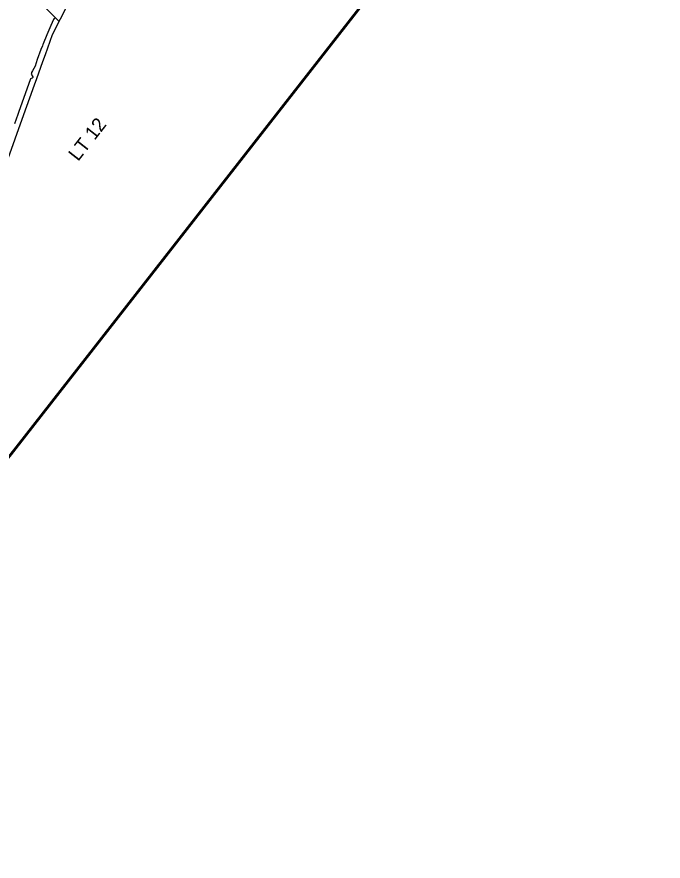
# Model space of a CAD drawing. Extents: x 586326 to 623965, y 4819854 to 4857850.
# Drawn here: x 606308 to 610982, y 4832762 to 4838866 of the extents above; entities that cross this region are included whole.
import ezdxf

# ---------------------------------------------------------------- set-up
doc = ezdxf.new("R2010")
doc.units = 0
for name, color, linetype in [('City Border', 7, 'Continuous'), ('Hydro ROW', 7, 'Continuous'), ('Lots_Concessions', 7, 'Continuous'), ('Major Rds and Hwys', 7, 'Continuous'), ('Municipal Bdry', 7, 'Continuous'), ('STREET NAME INDEX', 7, 'Continuous')]:
    doc.layers.add(name, color=color, linetype=linetype)

msp = doc.modelspace()

# ---------------------------------------------------------------- linework, layer by layer
at = {"layer": 'City Border'}
msp.add_lwpolyline([(586325.7, 4835119.3), (604090.7, 4857849.7), (616179.7, 4848401.5), (598414.7, 4825671.1)], close=True, dxfattribs=at)
at = {"layer": 'Hydro ROW'}
for p, q in [((606553.1, 4838804.2), (606525.7, 4838735.6)), ((606573.3, 4838846.3), (606553.1, 4838804.2)), ((606581.6, 4838853.1), (606573.3, 4838846.3)), ((606525.7, 4838735.6), (606498.6, 4838669.7)), ((606482.5, 4838630.6), (606455.3, 4838556.9)), ((606493.2, 4838656.6), (606482.5, 4838630.6)), ((606496.9, 4838665.7), (606493.2, 4838656.6)), ((606498.6, 4838669.7), (606496.9, 4838665.7)), ((606440.2, 4838508.4), (606421.2, 4838474.9)), ((606455.3, 4838556.9), (606440.2, 4838508.4)), ((606414.8, 4838455.9), (606412, 4838451.2)), ((606412, 4838451.2), (606423.2, 4838433.2)), ((606421.2, 4838474.9), (606414.5, 4838463.2)), ((606414.5, 4838463.2), (606414.8, 4838455.9)), ((606407.4, 4838418.7), (606319.9, 4838173.5)), ((606410.6, 4838420.1), (606407.4, 4838418.7)), ((606417.8, 4838423.4), (606410.6, 4838420.1)), ((606422.8, 4838428.2), (606417.8, 4838423.4)), ((606423.2, 4838433.2), (606422.8, 4838428.2)), ((606314.8, 4838159), (606291.2, 4838091.8)), ((606319.9, 4838173.5), (606314.8, 4838159))]:
    msp.add_line(p, q, dxfattribs=at)
at = {"layer": 'Major Rds and Hwys'}
msp.add_lwpolyline([(606614.3, 4838831.8), (606465.7, 4838981.2)], dxfattribs=at)
at = {"layer": 'Municipal Bdry'}
for p, q in [((606623.7, 4838851.3), (606959.3, 4839512.7)), ((606566, 4838737.6), (606606.3, 4838817)), ((606606.3, 4838817), (606610.2, 4838824.7)), ((606610.2, 4838824.7), (606623.7, 4838851.3)), ((606514.7, 4838594.1), (606566, 4838737.6)), ((606496.2, 4838542.2), (606514.7, 4838594.1)), ((606452.6, 4838420.4), (606496.2, 4838542.2)), ((606347.6, 4838126.4), (606436.5, 4838375.2)), ((606436.5, 4838375.2), (606452.6, 4838420.4)), ((606246, 4837842.1), (606347.6, 4838126.4))]:
    msp.add_line(p, q, dxfattribs=at)
at = {"layer": 'STREET NAME INDEX'}
msp.add_lwpolyline([(605975.1, 4819853.7), (623965, 4842871.9), (616456.8, 4848740), (598466.9, 4825721.8)], close=True, dxfattribs=at)

# ---------------------------------------------------------------- texts
at = {"layer": 'Lots_Concessions'}
msp.add_text('LT 12', height=100, rotation=52.00002, dxfattribs=at).set_placement((606751, 4837816.5))

doc.saveas('drawing.dxf')
